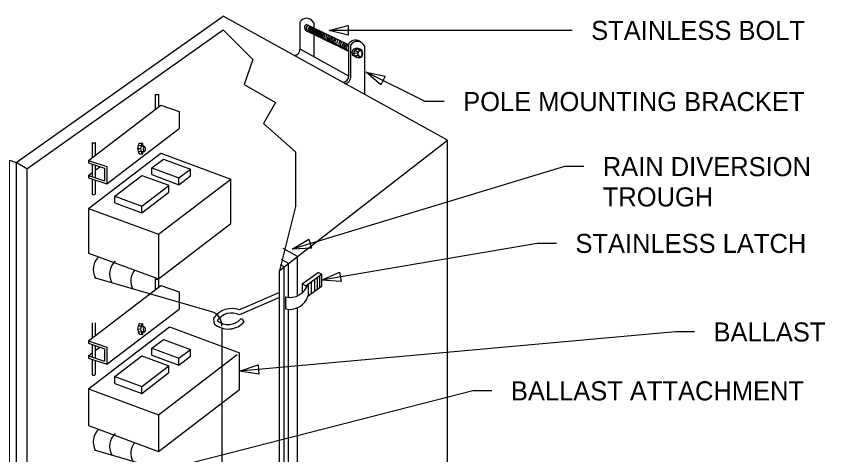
# Model space of a CAD drawing. Extents: x 10314 to 10360.8, y 10093.4 to 10137.8.
# Drawn here: x 10332.56 to 10360.85, y 10122.42 to 10137.76 of the extents above; entities that cross this region are included whole.
import ezdxf

# ---------------------------------------------------------------- set-up
doc = ezdxf.new("R2010")
doc.units = 0
for name, color, linetype in [('G-ANNO-TEXT', 7, 'Continuous'), ('G-DETL-LINE', 7, 'Continuous'), ('G-DETL-OTLN', 7, 'Continuous')]:
    doc.layers.add(name, color=color, linetype=linetype)

msp = doc.modelspace()

# ---------------------------------------------------------------- linework, layer by layer
at = {"layer": 'G-ANNO-TEXT'}
for p, q in [((10351.341, 10137.257), (10343.504, 10137.257)), ((10352.008, 10137.257), (10351.341, 10137.257)), ((10346.864, 10134.768), (10344.798, 10135.801)), ((10347.53, 10134.768), (10346.864, 10134.768)), ((10351.745, 10132.495), (10342.21, 10129.611)), ((10352.412, 10132.495), (10351.745, 10132.495)), ((10350.79, 10129.81), (10343.239, 10128.523)), ((10351.457, 10129.81), (10350.79, 10129.81)), ((10355.62, 10126.712), (10340.37, 10125.341)), ((10356.286, 10126.712), (10355.62, 10126.712)), ((10348.533, 10124.653), (10338.263, 10122.014)), ((10349.2, 10124.653), (10348.533, 10124.653))]:
    msp.add_line(p, q, dxfattribs=at)
for points in [[(10344.171, 10137.09), (10343.504, 10137.257), (10344.171, 10137.424)], [(10345.32, 10135.354), (10344.798, 10135.801), (10345.469, 10135.652)], [(10342.896, 10129.644), (10342.21, 10129.611), (10342.8, 10129.963)], [(10343.924, 10128.471), (10343.239, 10128.523), (10343.868, 10128.799)], [(10341.048, 10125.235), (10340.37, 10125.341), (10341.019, 10125.567)]]:
    msp.add_lwpolyline(points, close=True, dxfattribs=at)
at = {"layer": 'G-DETL-LINE'}
for p, q in [((10332.933, 10132.418), (10339.805, 10137.277)), ((10344.31, 10136.493), (10344.357, 10136.596)), ((10344.357, 10136.596), (10344.46, 10136.647)), ((10344.371, 10136.479), (10344.418, 10136.582)), ((10344.418, 10136.582), (10344.521, 10136.633)), ((10344.418, 10136.582), (10344.507, 10136.497)), ((10344.46, 10136.647), (10344.577, 10136.6)), ((10344.482, 10136.614), (10344.589, 10136.562)), ((10344.509, 10136.627), (10344.544, 10136.553)), ((10344.521, 10136.633), (10344.638, 10136.586)), ((10344.638, 10136.586), (10344.586, 10136.563)), ((10344.638, 10136.586), (10344.671, 10136.436)), ((10344.338, 10136.385), (10344.31, 10136.493)), ((10344.483, 10136.296), (10344.338, 10136.385)), ((10344.371, 10136.479), (10344.507, 10136.464)), ((10344.399, 10136.371), (10344.371, 10136.479)), ((10344.399, 10136.371), (10344.492, 10136.387)), ((10344.544, 10136.282), (10344.399, 10136.371)), ((10344.582, 10136.338), (10344.483, 10136.296)), ((10344.492, 10136.387), (10344.609, 10136.331)), ((10344.643, 10136.324), (10344.544, 10136.282)), ((10344.671, 10136.436), (10344.643, 10136.324)), ((10337.423, 10135.032), (10337.423, 10134.501)), ((10337.533, 10135.032), (10337.533, 10134.585)), ((10335.086, 10132.708), (10337.619, 10134.641)), ((10337.619, 10134.641), (10338.263, 10134.426)), ((10338.263, 10134.426), (10338.263, 10133.825)), ((10335.73, 10131.891), (10338.263, 10133.825)), ((10335.213, 10133.336), (10335.213, 10132.805)), ((10335.324, 10133.336), (10335.324, 10132.889)), ((10336.83, 10133.241), (10336.933, 10133.234)), ((10336.871, 10133.319), (10336.975, 10133.312)), ((10337.039, 10133.201), (10336.919, 10133.194)), ((10335.086, 10131.032), (10337.619, 10132.965)), ((10336.808, 10133.13), (10336.911, 10133.123)), ((10336.83, 10133.032), (10336.933, 10133.025)), ((10336.871, 10132.942), (10336.975, 10132.935)), ((10337.032, 10133.014), (10336.932, 10133.01)), ((10337.619, 10132.965), (10340.068, 10132.061)), ((10335.086, 10132.708), (10335.086, 10132.625)), ((10335.086, 10132.708), (10335.73, 10132.493)), ((10335.086, 10132.625), (10335.651, 10132.436)), ((10335.213, 10132.582), (10335.213, 10132.146)), ((10337.308, 10132.454), (10337.708, 10132.76)), ((10337.708, 10132.76), (10338.654, 10132.41)), ((10335.324, 10132.545), (10335.324, 10132.109)), ((10335.324, 10132.37), (10335.483, 10132.492)), ((10335.651, 10132.436), (10335.651, 10132)), ((10335.73, 10132.493), (10335.73, 10131.891)), ((10337.308, 10132.213), (10337.308, 10132.454)), ((10337.308, 10132.454), (10338.253, 10132.104)), ((10338.253, 10132.104), (10338.654, 10132.41)), ((10338.654, 10132.169), (10338.654, 10132.41)), ((10335.086, 10132.189), (10335.213, 10132.286)), ((10335.086, 10132.189), (10335.086, 10132.106)), ((10335.086, 10132.189), (10335.651, 10132)), ((10335.086, 10132.106), (10335.73, 10131.891)), ((10335.213, 10132.063), (10335.213, 10131.532)), ((10335.324, 10132.027), (10335.324, 10131.532)), ((10336.01, 10131.463), (10336.959, 10132.187)), ((10336.959, 10132.187), (10337.896, 10131.842)), ((10337.308, 10132.213), (10338.253, 10131.863)), ((10337.535, 10130.127), (10340.068, 10132.061)), ((10338.253, 10131.863), (10338.654, 10132.169)), ((10338.253, 10131.863), (10338.253, 10132.104)), ((10340.068, 10130.501), (10340.068, 10132.061)), ((10336.955, 10131.114), (10337.896, 10131.832)), ((10337.896, 10131.601), (10337.896, 10131.842)), ((10336.01, 10131.222), (10336.01, 10131.463)), ((10336.01, 10131.463), (10336.955, 10131.114)), ((10336.955, 10130.873), (10337.896, 10131.601)), ((10336.01, 10131.222), (10336.955, 10130.873)), ((10335.086, 10131.032), (10335.086, 10129.471)), ((10335.086, 10131.032), (10337.535, 10130.127)), ((10336.955, 10130.873), (10336.955, 10131.114)), ((10337.535, 10128.567), (10340.068, 10130.501)), ((10337.535, 10130.127), (10337.535, 10128.567)), ((10335.086, 10129.471), (10337.535, 10128.567)), ((10343.094, 10128.624), (10343.094, 10128.209)), ((10343.166, 10128.678), (10343.166, 10128.262)), ((10337.423, 10128.569), (10337.423, 10128.192)), ((10337.533, 10128.569), (10337.533, 10128.276)), ((10342.876, 10128.463), (10342.876, 10128.044)), ((10342.99, 10128.547), (10342.99, 10128.132)), ((10335.086, 10126.398), (10337.619, 10128.332)), ((10337.619, 10128.332), (10338.263, 10128.117)), ((10338.263, 10128.117), (10338.263, 10127.515)), ((10335.73, 10125.582), (10338.263, 10127.515)), ((10335.213, 10127.026), (10335.213, 10126.495)), ((10335.324, 10127.026), (10335.324, 10126.58)), ((10336.83, 10126.932), (10336.933, 10126.924)), ((10336.871, 10127.01), (10336.975, 10127.002)), ((10335.086, 10124.722), (10337.92, 10126.886)), ((10336.808, 10126.821), (10336.911, 10126.814)), ((10336.83, 10126.723), (10336.933, 10126.715)), ((10337.039, 10126.892), (10336.919, 10126.885)), ((10337.032, 10126.705), (10336.932, 10126.701)), ((10337.92, 10126.886), (10340.37, 10125.982)), ((10335.086, 10126.398), (10335.73, 10126.183)), ((10335.086, 10126.398), (10335.086, 10126.315)), ((10336.871, 10126.633), (10336.975, 10126.625)), ((10337.308, 10126.144), (10337.708, 10126.45)), ((10337.708, 10126.45), (10338.654, 10126.101)), ((10335.086, 10126.315), (10335.651, 10126.127)), ((10335.213, 10126.273), (10335.213, 10125.837)), ((10335.324, 10126.236), (10335.324, 10125.8)), ((10335.324, 10126.061), (10335.483, 10126.183)), ((10335.651, 10126.127), (10335.651, 10125.691)), ((10335.73, 10126.183), (10335.73, 10125.582)), ((10337.308, 10126.144), (10338.253, 10125.795)), ((10337.308, 10125.903), (10337.308, 10126.144)), ((10338.253, 10125.795), (10338.654, 10126.101)), ((10338.654, 10125.86), (10338.654, 10126.101)), ((10335.086, 10125.879), (10335.213, 10125.977)), ((10335.086, 10125.879), (10335.651, 10125.691)), ((10335.086, 10125.879), (10335.086, 10125.797)), ((10335.086, 10125.797), (10335.73, 10125.582)), ((10336.01, 10125.154), (10336.959, 10125.878)), ((10336.959, 10125.878), (10337.896, 10125.532)), ((10337.308, 10125.903), (10338.253, 10125.554)), ((10337.535, 10123.818), (10340.29, 10125.921)), ((10338.253, 10125.554), (10338.654, 10125.86)), ((10338.253, 10125.554), (10338.253, 10125.795)), ((10340.37, 10124.701), (10340.37, 10125.982)), ((10335.213, 10125.754), (10335.213, 10125.222)), ((10335.324, 10125.717), (10335.324, 10125.222)), ((10336.955, 10124.804), (10337.896, 10125.522)), ((10337.896, 10125.291), (10337.896, 10125.532)), ((10336.955, 10124.564), (10337.896, 10125.291)), ((10336.01, 10125.154), (10336.955, 10124.804)), ((10336.01, 10124.913), (10336.01, 10125.154)), ((10335.086, 10124.722), (10337.535, 10123.818)), ((10335.086, 10124.722), (10335.086, 10123.442)), ((10336.01, 10124.913), (10336.955, 10124.564)), ((10336.955, 10124.564), (10336.955, 10124.804)), ((10337.535, 10122.537), (10340.37, 10124.701)), ((10337.535, 10123.818), (10337.535, 10122.537)), ((10335.086, 10123.442), (10337.535, 10122.537))]:
    msp.add_line(p, q, dxfattribs=at)
msp.add_lwpolyline([(10339.805, 10137.277), (10340.836, 10136.238), (10340.535, 10135.369), (10341.634, 10134.731), (10341.208, 10133.997), (10342.325, 10133.011), (10342.325, 10131.096), (10341.773, 10128.866)], dxfattribs=at)
for centre, radius, start, end in [((10342.827, 10137.327), 0.121, 110.5726, 258.9535), ((10342.895, 10137.294), 0.121, 110.5726, 258.9535), ((10342.936, 10137.272), 0.121, 110.5726, 258.9535), ((10342.98, 10137.25), 0.121, 110.5726, 258.9535), ((10343.022, 10137.228), 0.121, 110.5726, 258.9535), ((10343.065, 10137.206), 0.121, 110.5726, 258.9535), ((10343.112, 10137.187), 0.121, 110.5726, 258.9535), ((10343.148, 10137.173), 0.121, 110.5726, 258.9535), ((10343.175, 10137.157), 0.121, 110.5726, 258.9535), ((10343.216, 10137.137), 0.121, 110.5726, 258.9535), ((10343.249, 10137.121), 0.121, 110.5726, 258.9535), ((10343.288, 10137.102), 0.121, 110.5726, 258.9535), ((10343.318, 10137.085), 0.121, 110.5726, 258.9535), ((10343.351, 10137.069), 0.121, 110.5726, 258.9535), ((10343.397, 10137.047), 0.121, 110.5726, 258.9535), ((10343.447, 10137.028), 0.121, 110.5726, 258.9535), ((10343.507, 10136.992), 0.121, 110.5726, 258.9535), ((10343.567, 10136.964), 0.121, 110.5726, 258.9535), ((10343.617, 10136.94), 0.121, 110.5726, 258.9535), ((10343.666, 10136.915), 0.121, 110.5726, 258.9535), ((10343.721, 10136.893), 0.121, 110.5726, 258.9535), ((10343.771, 10136.865), 0.121, 110.5726, 258.9535), ((10343.825, 10136.843), 0.121, 110.5726, 258.9535), ((10343.891, 10136.811), 0.121, 110.5726, 258.9535), ((10343.963, 10136.775), 0.121, 110.5726, 258.9535), ((10344.02, 10136.745), 0.121, 110.5726, 258.9535), ((10344.083, 10136.714), 0.121, 110.5726, 258.9535), ((10344.141, 10136.69), 0.121, 110.5726, 258.9535), ((10344.181, 10136.66), 0.121, 110.5726, 258.9535), ((10344.234, 10136.639), 0.121, 110.5726, 258.9535), ((10344.632, 10136.449), 0.121, 110.5726, 258.9535), ((10344.535, 10136.441), 0.133, 303.8869, 65.6391), ((10337.478, 10135.094), 0.0831, 228.34, 311.66), ((10335.269, 10133.398), 0.0831, 228.34, 311.66), ((10337.118, 10133.13), 0.31, 142.601, 217.3991), ((10337.221, 10133.123), 0.31, 142.601, 217.3991), ((10336.478, 10133.123), 0.532, 8.2302, 20.76), ((10337.175, 10133.102), 0.168, 143.9445, 211.5376), ((10336.981, 10133.11), 0.108, 298.1123, 57.3698), ((10336.478, 10133.123), 0.532, 339.24, 348.035), ((10335.269, 10131.594), 0.0831, 228.34, 311.66), ((10337.478, 10128.631), 0.0831, 228.34, 311.66), ((10337.118, 10126.821), 0.31, 142.601, 217.3991), ((10337.221, 10126.814), 0.31, 142.601, 217.3991), ((10336.478, 10126.814), 0.532, 8.2302, 20.76), ((10336.478, 10126.814), 0.532, 339.24, 348.035), ((10337.175, 10126.793), 0.168, 143.9445, 211.5376), ((10336.981, 10126.801), 0.108, 298.1123, 57.3698), ((10335.269, 10125.284), 0.0831, 228.34, 311.66)]:
    msp.add_arc(centre, radius, start, end, dxfattribs=at)
at = {"layer": 'G-DETL-OTLN'}
for p, q in [((10332.562, 10132.634), (10339.803, 10137.755)), ((10347.649, 10133.422), (10339.803, 10137.755)), ((10342.49, 10136.604), (10342.49, 10137.563)), ((10342.721, 10137.467), (10344.201, 10136.75)), ((10342.972, 10137.525), (10342.972, 10137.346)), ((10342.741, 10137.236), (10344.201, 10136.528)), ((10342.972, 10137.124), (10342.972, 10136.338)), ((10344.201, 10135.659), (10342.49, 10136.604)), ((10344.201, 10135.668), (10344.201, 10136.797)), ((10344.262, 10135.625), (10344.262, 10136.755)), ((10344.743, 10136.716), (10344.743, 10135.027)), ((10341.773, 10128.866), (10347.649, 10133.422)), ((10347.649, 10105.044), (10347.649, 10133.422)), ((10332.562, 10132.634), (10332.562, 10105.735)), ((10332.933, 10132.418), (10332.562, 10132.634)), ((10332.933, 10132.418), (10332.933, 10106.019)), ((10342.401, 10129.353), (10341.899, 10129.631)), ((10342.087, 10129.11), (10341.843, 10129.245)), ((10342.401, 10127.974), (10342.401, 10129.353)), ((10341.93, 10128.988), (10341.81, 10129.055)), ((10341.93, 10115.857), (10341.93, 10128.988)), ((10342.087, 10127.919), (10342.087, 10129.11)), ((10341.773, 10115.857), (10341.773, 10128.866)), ((10342.569, 10128.392), (10343.119, 10128.796)), ((10342.694, 10128.329), (10343.243, 10128.734)), ((10343.243, 10128.734), (10343.119, 10128.796)), ((10343.239, 10128.731), (10343.239, 10128.316)), ((10342.569, 10128.392), (10342.569, 10128.093)), ((10342.694, 10128.329), (10342.569, 10128.392)), ((10342.772, 10128.387), (10342.772, 10127.972)), ((10341.773, 10128.09), (10340.37, 10127.483)), ((10342.694, 10128.329), (10342.694, 10128.222)), ((10342.772, 10127.972), (10343.243, 10128.319)), ((10341.773, 10127.919), (10340.371, 10127.312)), ((10341.978, 10127.935), (10341.978, 10127.52)), ((10342.087, 10115.857), (10342.087, 10127.503)), ((10342.401, 10115.857), (10342.401, 10127.559)), ((10339.75, 10126.849), (10339.757, 10114.781))]:
    msp.add_line(p, q, dxfattribs=at)
msp.add_lwpolyline([(10332.562, 10132.634), (10332.562, 10105.735), (10332.318, 10105.87), (10332.324, 10132.724)], close=True, dxfattribs=at)
for points in [[(10335.292, 10128.616), (10339.393, 10127.422)], [(10335.292, 10122.586), (10339.393, 10121.392)]]:
    msp.add_lwpolyline(points, dxfattribs=at)
for centre, radius, start, end in [((10342.719, 10137.4), 0.282, 26.383, 144.468), ((10342.764, 10137.354), 0.121, 110.5726, 258.9535), ((10344.43, 10136.633), 0.282, 47.7347, 144.468), ((10344.491, 10136.591), 0.282, 26.383, 144.468), ((10342.265, 10136.607), 0.226, 275.9304, 359.1854), ((10343.975, 10135.671), 0.226, 275.9304, 359.1854), ((10344.036, 10135.629), 0.226, 275.9304, 359.1854), ((10335.872, 10128.895), 0.619, 133.4556, 207.2158), ((10336.445, 10128.738), 0.619, 133.4556, 207.2158), ((10337.187, 10128.49), 0.619, 141.598, 207.2158), ((10342.13, 10128.591), 0.673, 256.9446, 342.3923), ((10342.13, 10128.175), 0.673, 256.9446, 343.7178), ((10340.101, 10126.753), 0.778, 69.7124, 144.4339), ((10339.251, 10126.935), 0.507, 357.5847, 73.7678), ((10340.206, 10127.161), 0.74, 176.5465, 192.7165), ((10340.101, 10126.753), 0.621, 64.1717, 144.7376), ((10339.975, 10127.559), 0.744, 228.8503, 319.2199), ((10339.975, 10127.559), 0.587, 229.5848, 319.2199), ((10340.357, 10126.983), 0.202, 26.3148, 72.125), ((10335.872, 10122.865), 0.619, 133.4556, 207.2158), ((10336.445, 10122.708), 0.619, 133.4556, 207.2158), ((10337.187, 10122.46), 0.619, 141.598, 207.2158)]:
    msp.add_arc(centre, radius, start, end, dxfattribs=at)

# ---------------------------------------------------------------- texts
at = {"layer": 'G-ANNO-TEXT'}
for s, height, p in [('STAINLESS BOLT', 0.66667, (10352.674, 10136.924)), ('POLE MOUNTING BRACKET', 0.66667, (10348.197, 10134.435)), ('RAIN DIVERSION', 0.66667, (10353.079, 10132.161)), ('TROUGH', 0.6667, (10353.08, 10131.101)), ('STAINLESS LATCH', 0.66667, (10352.123, 10129.476)), ('BALLAST', 0.6667, (10356.953, 10126.379)), ('BALLAST ATTACHMENT', 0.66667, (10349.866, 10124.319))]:
    msp.add_text(s, height=height, dxfattribs=at).set_placement(p)

doc.saveas('drawing.dxf')
